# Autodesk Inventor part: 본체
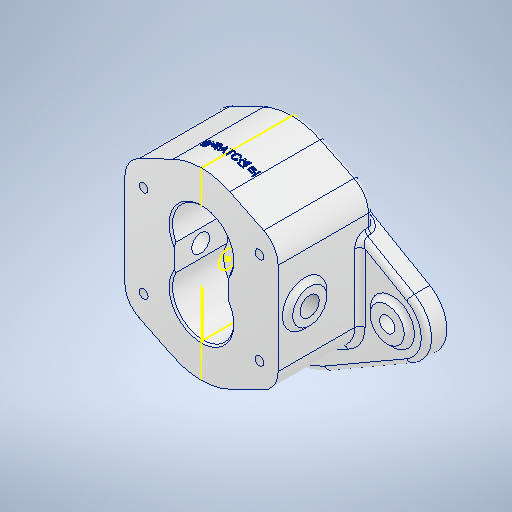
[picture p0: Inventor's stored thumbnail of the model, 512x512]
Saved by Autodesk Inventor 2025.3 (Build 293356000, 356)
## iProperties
Created: 2025-11
Part Number: 본체
Material: 알루미늄 6061
Document SubType Name: Modeling
Designer: PC-15
Density: 2.7 g/cm^3
Appearance: 알루미늄 - 평지
Mass: 1270.4 g
Surface Area: 590.969 cm^2
Volume: 470.52 cm^3
Author: PC-15
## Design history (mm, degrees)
sketch "스케치1" dims "d17" = 76
  geometry: L1 (-45, -27)-(45, -27); L2 (45, -27)-(45, 27); L3 (45, 27)-(-45, 27); L4 (-45, 27)-(-45, -27); L5 (-45, -27)-(45, 27); L6 (45, -27)-(-45, 27); L7 (0, 0)-(0, 16); L8 (0, 0)-(0, -16); L9 (0, 0)-(45, 0); L10 (36.553, 40.493)-(16.6, 50.183); L11 (-36.553, 40.493)-(-16.6, 50.183); L12 (-36.553, -40.493)-(-16.6, -50.183); L13 (36.553, -40.493)-(16.6, -50.183); C1 r 38 at (0, -16); C2 r 15 at (-30, 27); C3 r 15 at (-30, -27); C4 r 15 at (30, -27); A1 r 15 centre (30, 27) between (45, 27) and (36.553, 40.493); 12 further points
  constraints: 26 end point, 9 symmetric about line, 5 centre point, 5 midpoint, 2 coincident, 2 parallel, 2 point on circle, 2 vertical, 1 horizontal, 1 perpendicular, 1 point on line, 1 tangent, 7 other
  dimensions: "d13" = 54 distance of L1.end L2.end; "d14" = 90 distance of L2.end L3.end; "d16" = 16 distance of L7.start L7.end; "d22" = 16 distance of L7.start L8.end; "d23" = 76 diameter of C1; "d25" = 30 diameter of A1
extrude "돌출1" new body sketch "스케치1" distance "d26" = 48; taper "d27" = 0 deg
sketch "스케치2" dims "d31" = 40
  geometry: L1 (0, 0)-(0, -16); L2 (45, 27)-(45, -27) reference; L3 (36.553, -40.493)-(16.6, -50.183) reference; L4 (-16.6, -50.183)-(-36.553, -40.493) reference; L5 (-45, -27)-(-45, 27) reference; L6 (-36.553, 40.493)-(-16.6, 50.183) reference; L7 (16.6, 50.183)-(36.553, 40.493) reference; L8 (0, -16)-(-84, -16); L9 (0, -16)-(0, -54); L10 (0, -16)-(84, -16); L11 (74, 1.321)-(26, 29.033); L12 (74, -33.321)-(26, -61.033); L13 (-74, -33.321)-(-26, -61.033); L14 (-74, 1.321)-(-26, 29.033); A1 r 15 centre (30, 27) between (45, 27) and (36.553, 40.493) reference; A2 r 15 centre (30, -27) between (36.553, -40.493) and (45, -27) reference; A3 r 38 centre (0, -16) between (-16.6, -50.183) and (16.6, -50.183) reference; A4 r 15 centre (-30, -27) between (-45, -27) and (-36.553, -40.493) reference; A5 r 15 centre (-30, 27) between (-36.553, 40.493) and (-45, 27) reference; A6 r 38 centre (0, 16) between (16.6, 50.183) and (-16.6, 50.183) reference; A7 r 52 centre (0, -16) between (26, -61.033) and (26, 29.033); A8 r 20 centre (64, -16) between (84, -16) and (74, -33.321); 5 further points
  constraints: 16 end point, 6 point on circle, 6 symmetric about line, 4 tangent, 2 centre point, 2 point on line, 1 coincident, 1 horizontal, 1 vertical, 4 other
  dimensions: "d28" = 16 distance of L1.start L1.end; "d29" = 84 distance of L8.start L8.end; "d30" = 104 diameter of A7
extrude "돌출2" join sketch "스케치2" distance "d32" = 12; taper "d33" = 0 deg
sketch "스케치3"
  geometry: C1 r 10 at (64, -16); C2 r 10 at (-64, -16); A1 r 20 centre (-64, -16) between (-74, 1.321) and (-74, -33.321) reference; A2 r 20 centre (64, -16) between (74, -33.321) and (74, 1.321) reference; 1 further point
  constraints: 2 centre point, 2 coincident
  dimensions: "d34" = 20 diameter of C2; "d35" = 20 diameter of C1
extrude "돌출3" join sketch "스케치3" distance "d36" = 3; taper "d37" = 0 deg
sketch "스케치4"
  geometry: C1 r 10 at (0, 0) reference; C2 r 4.5 at (0, 0); C3 r 10 at (-128, 0) reference; C4 r 4.5 at (-128, 0); 1 further point
  constraints: 2 centre point, 2 coincident
  dimensions: "d38" = 9 diameter of C4; "d39" = 9 diameter of C2
extrude "돌출4" cut sketch "스케치4" extent not by distance; stored distance "d40" = 0; taper "d41" = 0 deg
sketch "스케치5" dims "d42" = 36, "d43" = 36
  geometry: L1 (16, 7.754)-(16, -7.754); L2 (0, 0)-(0, -16); L3 (-16, 7.754)-(-16, -7.754); A1 r 38 centre (0, 16) between (16.6, 50.183) and (-16.6, 50.183) reference; A2 r 38 centre (0, -16) between (-16.6, -50.183) and (16.6, -50.183) reference; 3 further points
  constraints: 6 end point, 2 coincident, 2 symmetric about line, 2 vertical, 6 other
  dimensions: "d44" = 16 distance from line of L1 L2.start
extrude "돌출5" cut sketch "스케치5" distance "d45" = 31; taper "d46" = 0 deg
sketch "스케치7"
  geometry: C1 r 25 at (0, -16); A1 r 52 centre (0, -16) between (-26, -61.033) and (26, -61.033) reference; 1 further point
  constraints: 1 centre point, 1 coincident
  dimensions: "d49" = 50 diameter of C1
extrude "돌출6" join sketch "스케치7" distance "d50" = 4; taper "d51" = 0 deg
sketch "스케치8"
  geometry: L1 (26, 29.033)-(45, 18.064) reference; L2 (45, 27)-(45, 18.064) reference; L3 (16.6, 50.183)-(36.553, 40.493) reference; L4 (-36.553, 40.493)-(-16.6, 50.183) reference; L5 (-45, 18.064)-(-45, 27) reference; L6 (-45, 18.064)-(-26, 29.033) reference; A1 r 15 centre (30, 27) between (45, 27) and (36.553, 40.493) reference; A2 r 38 centre (0, 16) between (16.6, 50.183) and (-16.6, 50.183) reference; A3 r 15 centre (-30, 27) between (-36.553, 40.493) and (-45, 27) reference; A4 r 52 centre (0, -16) between (26, 29.033) and (-26, 29.033) reference; 1 further point
extrude "돌출7" join sketch "스케치8" distance "d52" = 8; taper "d53" = 0 deg
sketch "스케치9"
  geometry: L1 (-68, -12)-(-68, 0) reference; L2 (-68, 0)-(-54, 0) reference; L3 (-54, 0)-(-54, 48) reference; L4 (-54, 48)-(-34, 48) reference; L5 (-34, 48)-(-34, 17) reference; L6 (-34, 17)-(34, 17) reference; L7 (34, 17)-(34, 48) reference; L8 (34, 48)-(54, 48) reference; L9 (54, 48)-(54, -8) reference; L10 (54, -8)-(36, -8) reference; L11 (36, -8)-(36, -12) reference; L12 (36, -12)-(9, -12) reference; L13 (9, -12)-(9, -16) reference; L14 (9, -16)-(-41, -16) reference; L15 (-41, -16)-(-41, -12) reference; L16 (-41, -12)-(-68, -12) reference; L17 (-68, -12)-(-68, 0) reference; L18 (-68, 0)-(-54, 0) reference; L19 (-54, 0)-(-54, 48) reference; L20 (-54, 48)-(-34, 48) reference; L21 (-34, 48)-(-34, 17) reference; L22 (-34, 17)-(34, 17) reference; L23 (34, 17)-(34, 48) reference; L24 (34, 48)-(54, 48) reference; L25 (54, 48)-(54, -8) reference; L26 (54, -8)-(36, -8) reference; L27 (36, -8)-(36, -12) reference; L28 (36, -12)-(9, -12) reference; L29 (9, -12)-(9, -16) reference; L30 (9, -16)-(-41, -16) reference; L31 (-41, -16)-(-41, -12) reference; L32 (-41, -12)-(-68, -12) reference; L33 (-68, -12)-(-68, 0) reference; L34 (-68, 0)-(-54, 0) reference; L35 (-54, 0)-(-54, 48) reference; L36 (-54, 48)-(-34, 48) reference; L37 (-34, 48)-(-34, 17) reference; L38 (-34, 17)-(34, 17) reference; L39 (34, 17)-(34, 48) reference; L40 (34, 48)-(54, 48) reference; L41 (54, 48)-(54, -8) reference; L42 (54, -8)-(36, -8) reference; L43 (36, -8)-(36, -12) reference; L44 (36, -12)-(9, -12) reference; L45 (9, -12)-(9, -16) reference; L46 (9, -16)-(-41, -16) reference; L47 (-41, -16)-(-41, -12) reference; L48 (-41, -12)-(-68, -12) reference; L49 (7.754, 48)-(7.754, 17) reference; L50 (-7.754, 48)-(-7.754, 17) reference; L51 (27, 48)-(-27, 48) reference; L52 (0, 48)-(0, -16); L53 (-7.754, 16)-(-7.754, 2); L54 (-7.754, 2)-(-19.254, 2); L55 (-19.254, 17)-(-19.254, -16); L56 (-4.254, -16)-(-4.254, -9); L57 (-4.554, -8.7)-(-19.254, -8.7); L58 (-8.754, 2)-(-8.754, -8.7); L59 (7.754, 16)-(7.754, 2); L60 (7.754, 2)-(19.254, 2); L61 (19.254, 17)-(19.254, -12); L62 (6.754, 17)-(-6.754, 17); L63 (7.754, 16)-(6.754, 17); L64 (-6.754, 17)-(-7.754, 16); A1 r 0.3 centre (-4.554, -9) between (-4.254, -9) and (-4.554, -8.7); 8 further points
  constraints: 26 end point, 17 point on line, 7 perpendicular, 3 vertical, 2 point on circle, 2 tangent, 1 centre point, 1 collinear, 1 midpoint
  dimensions: "d54" = 15 distance of L50.end L53.end; "d56" = 11.5 distance of L53.end L54.end; "d57" = 30 diameter of L56 L55; "d58" = 7.3 distance of L56.start point (-4.254, -8.7); "d59" = 21 diameter of L58 L55; "d60" = 0.3 radius of A1; "d61" = 11.5 distance of L59.end L60.end; "d62" = 15 distance of L49.end L59.end; "d63" = 1 distance of L59.start L49.end; "d64" = 1 distance of L62.start L49.end (= d63); "d65" = 1 distance of L62.end L50.end (= d63); "d66" = 1 distance of L53.start L50.end (= d65)
  node "절단 모서리 투영4"
  node "절단 모서리 투영5"
  node "절단 모서리 투영6"
revolve "회전2" stored, may be unused: angle "d68" = 90 deg
sketch "스케치10"
  geometry: 1 further point
revolve "회전3" stored, may be unused: angle "d69" = 90 deg
sketch "스케치11"
  geometry: 1 further point
sketch "스케치12"
  geometry: 5 further points
  constraints: 2 vertical alignment
  dimensions: "d70" = 54 distance of point (34, -27) point (34, 27); "d71" = 27 vertical distance of point (0, 0) point (34, 27); "d72" = 34 horizontal distance of point (0, 0) point (34, 27); "d73" = 68 distance of point (34, 27) point (-34, 27); "d74" = 54 distance of point (-34, 27) point (-34, -27); "d75" = 27 vertical distance of point (0, 0) point (-34, 27)
hole "구멍1" sketch "스케치12" at (34, 27), (34, -27), (-34, 27), (-34, -27) diameter "d76" = 5.24223; stored, may be unused: countersink angle "d80" = 90 deg, drill point angle "d82" = 118 deg; dims "d77" = 12, "d78" = 4, "d79" = 2, "d81" = 14
sketch "스케치13"
  geometry: L1 (0, 0)-(0, 54) reference; L2 (60, -23.064)-(48, -23.064) reference; L3 (48, -23.064)-(48, 0) reference; L4 (48, 0)-(48, 45.064) reference; L5 (48, 45.064)-(56, 45.064) reference; L6 (56, 45.064)-(60, 45.064) reference; L7 (60, 45.064)-(60, -23.064) reference; L8 (48, 0)-(0, 0) reference; L9 (0, 0)-(0, 54) reference; L10 (56, 54)-(0, 54) reference; L11 (56, 54)-(56, 45.064) reference; L12 (0, 34.754)-(31, 34.754) reference; C1 r 10 at (15.5, 27); 3 further points
  constraints: 2 midpoint, 1 centre point, 1 horizontal alignment, 1 vertical alignment
  dimensions: "d83" = 20 diameter of C1
extrude "돌출8" join sketch "스케치13" distance "d84" = 3; taper "d85" = 0 deg
sketch "스케치14"
  geometry: C1 r 10 at (0, 0) reference; 1 further point
hole "구멍2" sketch "스케치14" at (0, 0) diameter "d86" = 10.5; stored, may be unused: countersink angle "d92" = 90 deg, drill point angle "d94" = 118 deg; dims "d87" = 11, "d88" = 0.62479, "d89" = 10.589, "d90" = 4, "d91" = 2, "d93" = 39.25
fillet "모깎기1" dims "d95" = 3
chamfer "모따기1" distance "d96" = 1; stored, may be unused: second distance "d97" = 2, angle "d98" = 45 deg
fillet "모깎기2" dims "d99" = 3
fillet "모깎기3" dims "d100" = 3
sketch "스케치15"
  geometry: L1 (-16.6, 48)-(-36.553, 48) reference; L2 (17.91, 0)-(-17.91, 0) reference; 3 further points
  constraints: 1 coincident, 1 midpoint, 1 vertical alignment, 1 other
  dimensions: "d101" = 16 distance from line of L1 point (0, 32)
feature "엠보싱1" sketch "스케치15" dims "d13" = 54, "d14" = 90, "d16" = 16, "d17" = 76, "d25" = 30, "d102" = 0.5, "d103" = 0
sketch "스케치16"
  geometry: L1 (-34.254, -9)-(-34.254, -16) reference; L2 (-34.254, -16)-(-41, -16) reference; L3 (-41, -16)-(-41, -15) reference; L4 (-44, -12)-(-68, -12) reference; L5 (-68, -12)-(-68, -3) reference; L6 (-65, 0)-(-57, 0) reference; L7 (-54, 3)-(-54, 48) reference; L8 (-54, 48)-(-35, 48) reference; L9 (-35, 48)-(-34, 47) reference; L10 (-34, 47)-(-34, 17) reference; L11 (-34, 17)-(-31.754, 17) reference; L12 (-31.754, 17)-(-30.754, 16) reference; L13 (-30.754, 16)-(-30.754, 2) reference; L14 (-30.754, 2)-(-29.754, 2) reference; L15 (-29.754, 2)-(-29.754, -8.7) reference; L16 (-29.754, -8.7)-(-33.954, -8.7) reference; L17 (30.754, 2)-(30.754, 16) reference; L18 (30.754, 16)-(31.754, 17) reference; L19 (31.754, 17)-(34, 17) reference; L20 (34, 17)-(34, 47) reference; L21 (34, 47)-(35, 48) reference; L22 (35, 48)-(54, 48) reference; L23 (54, 48)-(54, 30.423) reference; L24 (54, 30.423)-(54.5, 30.423) reference; L25 (54.5, 30.423)-(54.5, 30.092) reference; L26 (54.5, 30.092)-(54, 30.092) reference; L27 (54, 30.092)-(54, -5) reference; L28 (51, -8)-(39, -8) reference; L29 (36, -11)-(36, -12) reference; L30 (36, -12)-(12, -12) reference; L31 (9, -15)-(9, -16) reference; L32 (9, -16)-(-4.254, -16) reference; L33 (-4.254, -16)-(-4.254, -9) reference; L34 (-4.554, -8.7)-(-8.754, -8.7) reference; L35 (-8.754, -8.7)-(-8.754, 2) reference; L36 (-8.754, 2)-(-7.754, 2) reference; L37 (-7.754, 2)-(-7.754, 16) reference; L38 (-7.754, 16)-(-6.754, 17) reference; L39 (-6.754, 17)-(6.754, 17) reference; L40 (6.754, 17)-(7.754, 16) reference; L41 (7.754, 16)-(7.754, 2) reference; L42 (7.754, 2)-(30.754, 2) reference; L43 (-34, 47)-(-7.754, 47) reference; L44 (-5.753, 48)-(-35, 48) reference; C1 r 5.25 at (0, 32.5) reference; A1 r 3 centre (-44, -15) between (-41, -15) and (-44, -12) reference; A2 r 3 centre (-65, -3) between (-65, 0) and (-68, -3) reference; A3 r 3 centre (-57, 3) between (-57, 0) and (-54, 3) reference; A4 r 0.3 centre (-33.954, -9) between (-33.954, -8.7) and (-34.254, -9) reference; A5 r 3 centre (51, -5) between (51, -8) and (54, -5) reference; A6 r 3 centre (39, -11) between (39, -8) and (36, -11) reference; A7 r 3 centre (12, -15) between (12, -12) and (9, -15) reference; A8 r 0.3 centre (-4.554, -9) between (-4.254, -9) and (-4.554, -8.7) reference; 1 further point
  node "절단 모서리 투영8"
node "솔리드1"
mirror "미러1"
node "절단 모서리 투영1"
node "절단 모서리 투영7"
feature "A9D066F2-1C7D-4E18-AEED-F7BC21143FA4" dims "d76" = 5.24223, "d77" = 12, "d78" = 4, "d79" = 2, "d80" = 90 deg, "d81" = 14, "d82" = 118 deg
